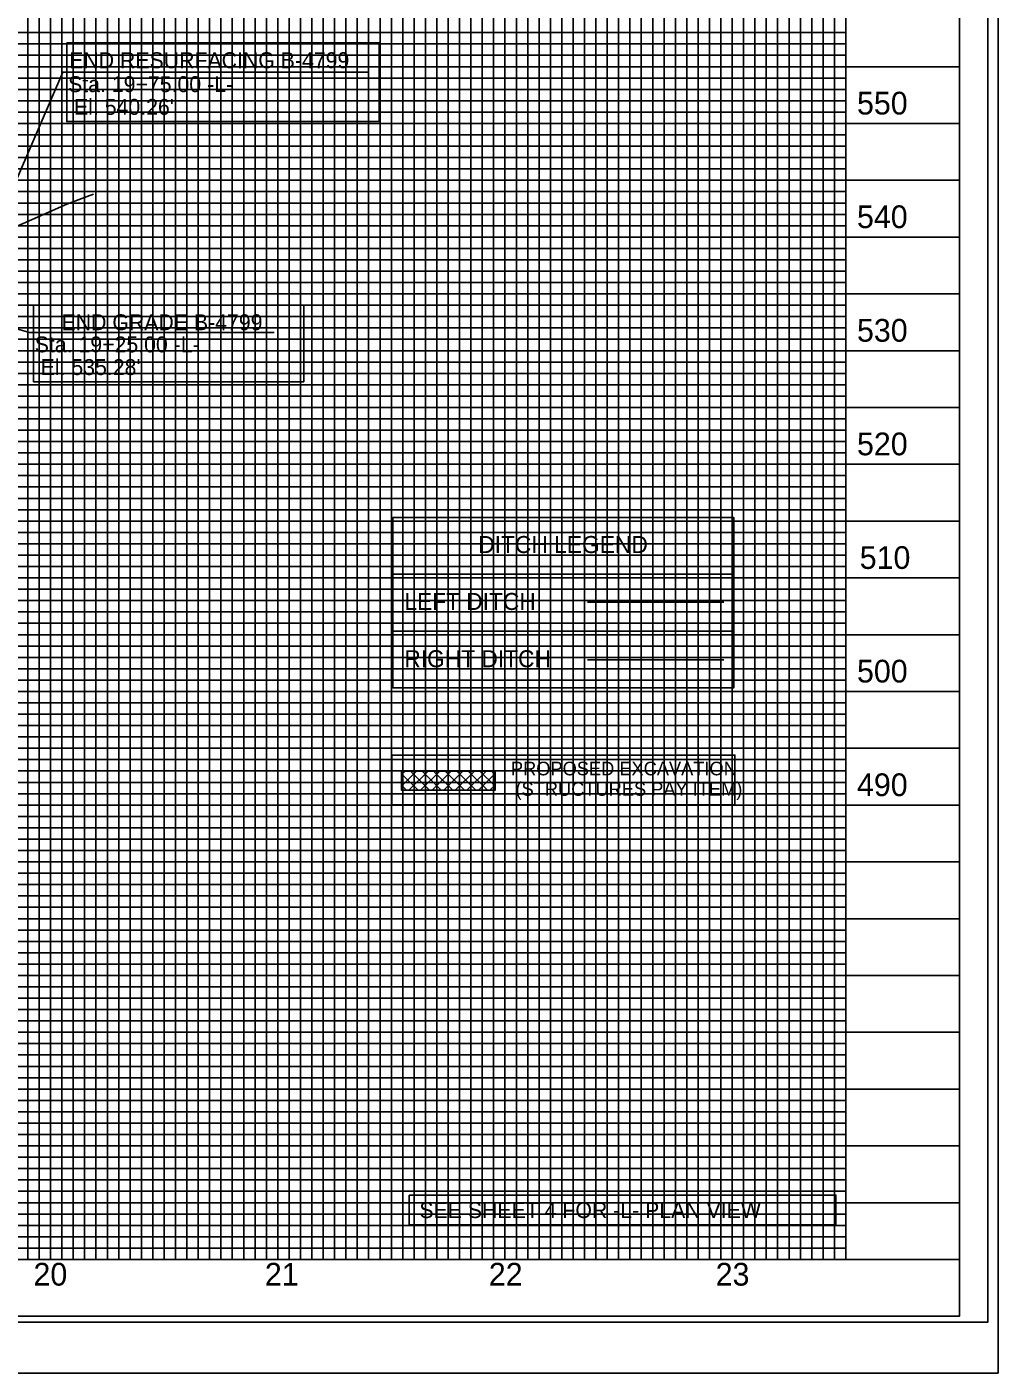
# Model space of a CAD drawing. Extents: x 573715 to 575626, y -55474 to -54374.
# Drawn here: x 574972 to 575399, y -55474 to -54882 of the extents above; entities that cross this region are included whole.
import ezdxf

# ---------------------------------------------------------------- set-up
doc = ezdxf.new("R2010")
doc.units = 0
for name, color, linetype in [('Exist Profile Cell', 7, 'Continuous'), ('Exist Vertical Profile Ground Line', 7, 'Continuous'), ('Exist Vertical Profile Horizontal Axis Label Major', 7, 'Continuous'), ('Exist Vertical Profile Vertical Axis Label', 7, 'Continuous'), ('Prop Grid Mask', 7, 'Continuous'), ('Prop Hatching', 7, 'Continuous'), ('Prop PFL Ditch Label CELL', 7, 'Continuous'), ('Prop Vertical Profile Curve Label', 7, 'Continuous'), ('Prop VPI Label', 7, 'Continuous'), ('Sheet Cutting Line CELL', 7, 'Continuous'), ('Sheet DOT Grid CELL', 7, 'Continuous'), ('Sheet Layout Profile Border', 7, 'Continuous'), ('Sheet Plot Border Inside CELL', 7, 'Continuous'), ('Sheet Plot Border Outside CELL', 7, 'Continuous'), ('Sheet Profile CELL', 7, 'Continuous'), ('Sheet Profile Grid Major CELL', 7, 'Continuous'), ('Sheet Profile Grid Middle CELL', 7, 'Continuous'), ('Sheet Profile Grid Minor CELL', 7, 'Continuous')]:
    doc.layers.add(name, color=color, linetype=linetype)

msp = doc.modelspace()

# ---------------------------------------------------------------- linework, layer by layer
at = {"layer": 'Exist Profile Cell'}
msp.add_line((573982.27, -55224.42), (575001.21, -55224.42), dxfattribs=at)
at = {"layer": 'Exist Vertical Profile Ground Line'}
msp.add_lwpolyline([(574959.85, -54973.04), (574989.51, -54959.89), (574998.39, -54956.62), (575001.21, -54955.58)], dxfattribs=at)
at = {"layer": 'Prop Grid Mask'}
for points in [[(574989.38, -54888.91), (575126.86, -54888.91), (575126.86, -54923.59), (574989.38, -54923.59)], [(574974.7, -55004.37), (575093.67, -55004.37), (575093.67, -55038.13), (574974.7, -55038.13)], [(575132.98, -55097.84), (575282.98, -55097.84), (575282.98, -55122.84), (575132.98, -55122.84)], [(575132.98, -55122.84), (575282.98, -55122.84), (575282.98, -55147.84), (575132.98, -55147.84)], [(575132.98, -55147.84), (575282.98, -55147.84), (575282.98, -55172.84), (575132.98, -55172.84)], [(575132.47, -55224.27), (575283.43, -55224.27), (575283.43, -55202.45), (575132.47, -55202.45)], [(575177.93, -55209.45), (575136.75, -55209.45), (575136.75, -55217.9), (575177.93, -55217.9)], [(575140.11, -55396.07), (575327.9, -55396.07), (575327.9, -55409.2), (575140.11, -55409.2)]]:
    msp.add_lwpolyline(points, close=True, dxfattribs=at)
at = {"layer": 'Prop Hatching'}
for p, q in [((575136.75, -55210.98), (575138.28, -55209.45)), ((575136.75, -55216.07), (575143.37, -55209.45)), ((575136.75, -55210.63), (575144.02, -55217.9)), ((575140.02, -55217.9), (575148.46, -55209.45)), ((575140.67, -55209.45), (575149.12, -55217.9)), ((575145.11, -55217.9), (575153.55, -55209.45)), ((575145.76, -55209.45), (575154.21, -55217.9)), ((575150.2, -55217.9), (575158.65, -55209.45)), ((575150.85, -55209.45), (575159.3, -55217.9)), ((575155.29, -55217.9), (575163.74, -55209.45)), ((575155.94, -55209.45), (575164.39, -55217.9)), ((575160.38, -55217.9), (575168.83, -55209.45)), ((575161.04, -55209.45), (575169.48, -55217.9)), ((575165.48, -55217.9), (575173.92, -55209.45)), ((575166.13, -55209.45), (575174.57, -55217.9)), ((575170.57, -55217.9), (575177.93, -55210.54)), ((575171.22, -55209.45), (575177.93, -55216.16)), ((575176.31, -55209.45), (575177.93, -55211.07)), ((575136.75, -55215.72), (575138.93, -55217.9)), ((575175.66, -55217.9), (575177.93, -55215.63))]:
    msp.add_line(p, q, dxfattribs=at)
at = {"layer": 'Prop PFL Ditch Label CELL'}
for p, q in [((575218.53, -55135.14), (575278.53, -55135.14)), ((575218.53, -55160.49), (575278.53, -55160.49)), ((575132.98, -55162.84), (575132.98, -55162.84))]:
    msp.add_line(p, q, dxfattribs=at)
at = {"layer": 'Prop Vertical Profile Curve Label'}
for p, q in [((574987.75, -54901.88), (574957.02, -54972.88)), ((574987.75, -54901.88), (575121.7, -54901.88)), ((574907.27, -54998.02), (574973.06, -55016.41)), ((574973.06, -55016.41), (575080.66, -55016.41))]:
    msp.add_line(p, q, dxfattribs=at)
at = {"layer": 'Sheet Cutting Line CELL'}
msp.add_line((573715.27, -55474.42), (575399.27, -55474.42), dxfattribs=at)
at = {"layer": 'Sheet DOT Grid CELL'}
for p, q in [((574982.27, -54399.42), (574982.27, -55424.42)), ((575032.27, -54399.42), (575032.27, -55424.42)), ((575082.27, -54399.42), (575082.27, -55424.42)), ((575132.27, -54399.42), (575132.27, -55424.42)), ((575182.27, -55424.42), (575182.27, -54536.97)), ((575232.27, -55424.42), (575232.27, -54536.97)), ((575282.27, -55424.42), (575282.27, -54536.97)), ((575332.27, -55424.42), (575332.27, -54536.97)), ((573882.27, -54924.42), (575382.27, -54924.42)), ((573882.27, -54974.42), (575382.27, -54974.42)), ((573882.27, -55024.42), (575382.27, -55024.42)), ((573882.27, -55074.42), (575382.27, -55074.42)), ((573882.27, -55124.42), (575382.27, -55124.42)), ((573882.27, -55174.42), (575382.27, -55174.42)), ((573882.27, -55224.42), (575382.27, -55224.42)), ((573882.27, -55274.42), (575382.27, -55274.42)), ((573882.27, -55324.42), (575382.27, -55324.42)), ((573882.27, -55374.42), (575382.27, -55374.42))]:
    msp.add_line(p, q, dxfattribs=at)
at = {"layer": 'Sheet Layout Profile Border'}
msp.add_lwpolyline([(573932.27, -54399.42), (573932.27, -55424.42), (575332.27, -55424.42), (575332.27, -54536.97), (575182.22, -54536.97), (575182.22, -54399.42)], close=True, dxfattribs=at)
at = {"layer": 'Sheet Plot Border Inside CELL'}
msp.add_lwpolyline([(575394.77, -54396.87), (573728.27, -54396.87), (573728.27, -55451.97), (575394.77, -55451.97)], close=True, dxfattribs=at)
msp.add_lwpolyline([(575394.77, -54396.87), (573728.27, -54396.87), (573728.27, -55451.97), (575394.77, -55451.97)], close=True, dxfattribs=at)
at = {"layer": 'Sheet Plot Border Outside CELL'}
msp.add_lwpolyline([(575399.27, -54374.42), (573715.27, -54374.42), (573715.27, -55474.42), (575399.27, -55474.42)], close=True, dxfattribs=at)
at = {"layer": 'Sheet Profile CELL'}
msp.add_line((575382.27, -55424.42), (573882.27, -55424.42), dxfattribs=at)
msp.add_lwpolyline([(575382.27, -54399.42), (573882.27, -54399.42), (573882.27, -55449.42), (575382.27, -55449.42)], close=True, dxfattribs=at)
at = {"layer": 'Sheet Profile Grid Major CELL'}
for points in [[(574932.27, -55424.42), (574982.27, -55424.42), (574982.27, -54399.42), (575032.27, -54399.42), (575032.27, -55424.42), (575082.27, -55424.42), (575082.27, -54399.42), (575132.27, -54399.42), (575132.27, -55424.42), (575182.27, -55424.42), (575182.27, -54399.42), (575208.57, -54399.42)], [(575232.27, -54536.97), (575232.27, -55424.42), (575282.27, -55424.42), (575282.27, -54536.97)], [(575332.27, -54536.97), (575332.27, -55424.42), (575382.27, -55424.42)], [(575382.27, -54974.42), (573882.27, -54974.42), (573882.27, -54924.42), (575382.27, -54924.42)], [(575382.27, -55074.42), (573882.27, -55074.42), (573882.27, -55024.42), (575382.27, -55024.42)], [(575382.27, -55174.42), (573882.27, -55174.42), (573882.27, -55124.42), (575382.27, -55124.42)], [(575382.27, -55274.42), (573882.27, -55274.42), (573882.27, -55224.42), (575382.27, -55224.42)], [(575382.27, -55374.42), (573882.27, -55374.42), (573882.27, -55324.42), (575382.27, -55324.42)]]:
    msp.add_lwpolyline(points, dxfattribs=at)
at = {"layer": 'Sheet Profile Grid Middle CELL'}
for points in [[(574957.27, -54399.42), (575007.27, -54399.42), (575007.27, -55424.42), (575057.27, -55424.42), (575057.27, -54399.42), (575107.27, -54399.42), (575107.27, -55424.42), (575157.27, -55424.42), (575157.27, -54399.42)], [(575207.27, -54536.97), (575207.27, -55424.42), (575257.27, -55424.42), (575257.27, -54536.97)], [(575307.27, -54536.97), (575307.27, -55424.42)], [(575382.27, -54899.42), (573882.27, -54899.42), (573882.27, -54949.42), (575382.27, -54949.42)], [(575382.27, -54999.42), (573882.27, -54999.42), (573882.27, -55049.42), (575382.27, -55049.42)], [(575382.27, -55099.42), (573882.27, -55099.42), (573882.27, -55149.42), (575382.27, -55149.42)], [(575382.27, -55199.42), (573882.27, -55199.42), (573882.27, -55249.42), (575382.27, -55249.42)], [(575382.27, -55299.42), (573882.27, -55299.42), (573882.27, -55349.42), (575382.27, -55349.42)], [(575382.27, -55399.42), (573882.27, -55399.42)]]:
    msp.add_lwpolyline(points, dxfattribs=at)
at = {"layer": 'Sheet Profile Grid Minor CELL'}
for points in [[(574967.27, -55424.42), (574972.27, -55424.42), (574972.27, -54399.42)], [(574977.27, -54399.42), (574977.27, -55424.42), (574987.27, -55424.42), (574987.27, -54399.42)], [(574992.27, -54399.42), (574992.27, -55424.42), (574997.27, -55424.42), (574997.27, -54399.42)], [(575002.27, -54399.42), (575002.27, -55424.42), (575012.27, -55424.42), (575012.27, -54399.42)], [(575017.27, -54399.42), (575017.27, -55424.42), (575022.27, -55424.42), (575022.27, -54399.42)], [(575027.27, -54399.42), (575027.27, -55424.42), (575037.27, -55424.42), (575037.27, -54399.42)], [(575042.27, -54399.42), (575042.27, -55424.42), (575047.27, -55424.42), (575047.27, -54399.42)], [(575052.27, -54399.42), (575052.27, -55424.42), (575062.27, -55424.42), (575062.27, -54399.42)], [(575067.27, -54399.42), (575067.27, -55424.42), (575072.27, -55424.42), (575072.27, -54399.42)], [(575077.27, -54399.42), (575077.27, -55424.42), (575087.27, -55424.42), (575087.27, -54399.42)], [(575092.27, -54399.42), (575092.27, -55424.42), (575097.27, -55424.42), (575097.27, -54399.42)], [(575102.27, -54399.42), (575102.27, -55424.42), (575112.27, -55424.42), (575112.27, -54399.42)], [(575117.27, -54399.42), (575117.27, -55424.42), (575122.27, -55424.42), (575122.27, -54399.42)], [(575127.27, -54399.42), (575127.27, -55424.42), (575137.27, -55424.42), (575137.27, -54399.42)], [(575142.27, -54399.42), (575142.27, -55424.42), (575147.27, -55424.42), (575147.27, -54399.42)], [(575152.27, -54399.42), (575152.27, -55424.42), (575162.27, -55424.42), (575162.27, -54399.42)], [(575167.27, -54399.42), (575167.27, -55424.42), (575172.27, -55424.42), (575172.27, -54399.42)], [(575177.27, -54399.42), (575177.27, -55424.42), (575187.27, -55424.42), (575187.27, -54536.97)], [(575192.27, -54536.97), (575192.27, -55424.42), (575197.27, -55424.42), (575197.27, -54536.97)], [(575202.27, -54536.97), (575202.27, -55424.42), (575212.27, -55424.42), (575212.27, -54536.97)], [(575217.27, -54536.97), (575217.27, -55424.42), (575222.27, -55424.42), (575222.27, -54536.97)], [(575227.27, -54536.97), (575227.27, -55424.42), (575237.27, -55424.42), (575237.27, -54536.97)], [(575242.27, -54536.97), (575242.27, -55424.42), (575247.27, -55424.42), (575247.27, -54536.97)], [(575252.27, -54536.97), (575252.27, -55424.42), (575262.27, -55424.42), (575262.27, -54536.97)], [(575267.27, -54536.97), (575267.27, -55424.42)], [(575267.27, -55424.42), (575272.27, -55424.42), (575272.27, -54536.97)], [(575277.27, -54536.97), (575277.27, -55424.42), (575287.27, -55424.42), (575287.27, -54536.97)], [(575292.27, -54536.97), (575292.27, -55424.42), (575297.27, -55424.42), (575297.27, -54536.97)], [(575302.27, -54536.97), (575302.27, -55424.42), (575312.27, -55424.42), (575312.27, -54536.97)], [(575317.27, -54536.97), (575317.27, -55424.42), (575322.27, -55424.42), (575322.27, -54536.97)], [(575327.27, -54536.97), (575327.27, -55424.42), (575337.27, -55424.42)], [(575332.27, -54884.42), (573932.27, -54884.42), (573932.27, -54889.42), (575332.27, -54889.42)], [(575332.27, -54894.42), (573932.27, -54894.42), (573932.27, -54904.42), (575332.27, -54904.42)], [(575332.27, -54909.42), (573932.27, -54909.42), (573932.27, -54914.42), (575332.27, -54914.42)], [(575332.27, -54919.42), (573932.27, -54919.42)], [(573932.27, -54929.42), (575332.27, -54929.42)], [(575332.27, -54934.42), (573932.27, -54934.42), (573932.27, -54939.42), (575332.27, -54939.42)], [(575332.27, -54944.42), (573932.27, -54944.42), (573932.27, -54954.42), (575332.27, -54954.42)], [(575332.27, -54959.42), (573932.27, -54959.42), (573932.27, -54964.42), (575332.27, -54964.42)], [(575332.27, -54969.42), (573932.27, -54969.42), (573932.27, -54979.42), (575332.27, -54979.42)], [(575332.27, -54984.42), (573932.27, -54984.42), (573932.27, -54989.42), (575332.27, -54989.42)], [(575332.27, -54994.42), (573932.27, -54994.42), (573932.27, -55004.42), (575332.27, -55004.42)], [(575332.27, -55009.42), (573932.27, -55009.42), (573932.27, -55014.42), (575332.27, -55014.42)], [(575332.27, -55019.42), (573932.27, -55019.42), (573932.27, -55029.42), (575332.27, -55029.42)], [(575332.27, -55034.42), (573932.27, -55034.42), (573932.27, -55039.42), (575332.27, -55039.42)], [(575332.27, -55044.42), (573932.27, -55044.42), (573932.27, -55054.42), (575332.27, -55054.42)], [(575332.27, -55059.42), (573932.27, -55059.42), (573932.27, -55064.42), (575332.27, -55064.42)], [(575332.27, -55069.42), (573932.27, -55069.42), (573932.27, -55079.42), (575332.27, -55079.42)], [(575332.27, -55084.42), (573932.27, -55084.42), (573932.27, -55089.42), (575332.27, -55089.42)], [(575332.27, -55094.42), (573932.27, -55094.42), (573932.27, -55104.42), (575332.27, -55104.42)], [(575332.27, -55109.42), (573932.27, -55109.42), (573932.27, -55114.42), (575332.27, -55114.42)], [(575332.27, -55119.42), (573932.27, -55119.42), (573932.27, -55129.42), (575332.27, -55129.42)], [(575332.27, -55134.42), (573932.27, -55134.42), (573932.27, -55139.42), (575332.27, -55139.42)], [(575332.27, -55144.42), (573932.27, -55144.42), (573932.27, -55154.42), (575332.27, -55154.42)], [(575332.27, -55159.42), (573932.27, -55159.42), (573932.27, -55164.42), (575332.27, -55164.42)], [(575332.27, -55169.42), (573932.27, -55169.42), (573932.27, -55179.42), (575332.27, -55179.42)], [(575332.27, -55184.42), (573932.27, -55184.42), (573932.27, -55189.42), (575332.27, -55189.42)], [(575332.27, -55194.42), (573932.27, -55194.42), (573932.27, -55204.42), (575332.27, -55204.42)], [(575332.27, -55209.42), (573932.27, -55209.42), (573932.27, -55214.42), (575332.27, -55214.42)], [(575332.27, -55219.42), (573932.27, -55219.42)], [(573932.27, -55229.42), (575332.27, -55229.42)], [(575332.27, -55234.42), (573932.27, -55234.42), (573932.27, -55239.42), (575332.27, -55239.42)], [(575332.27, -55244.42), (573932.27, -55244.42)], [(573932.27, -55254.42), (575332.27, -55254.42)], [(575332.27, -55259.42), (573932.27, -55259.42), (573932.27, -55264.42), (575332.27, -55264.42)], [(575332.27, -55269.42), (573932.27, -55269.42), (573932.27, -55279.42), (575332.27, -55279.42)], [(575332.27, -55284.42), (573932.27, -55284.42), (573932.27, -55289.42), (575332.27, -55289.42)], [(575332.27, -55294.42), (573932.27, -55294.42), (573932.27, -55304.42), (575332.27, -55304.42)], [(575332.27, -55309.42), (573932.27, -55309.42), (573932.27, -55314.42), (575332.27, -55314.42)], [(575332.27, -55319.42), (573932.27, -55319.42), (573932.27, -55329.42), (575332.27, -55329.42)], [(575332.27, -55334.42), (573932.27, -55334.42), (573932.27, -55339.42), (575332.27, -55339.42)], [(575332.27, -55344.42), (573932.27, -55344.42), (573932.27, -55354.42), (575332.27, -55354.42)], [(575332.27, -55359.42), (573932.27, -55359.42), (573932.27, -55364.42), (575332.27, -55364.42)], [(575332.27, -55369.42), (573932.27, -55369.42), (573932.27, -55379.42), (575332.27, -55379.42)], [(575332.27, -55384.42), (573932.27, -55384.42), (573932.27, -55389.42), (575332.27, -55389.42)], [(575332.27, -55394.42), (573932.27, -55394.42), (573932.27, -55404.42), (575332.27, -55404.42)], [(575332.27, -55409.42), (573932.27, -55409.42), (573932.27, -55414.42), (575332.27, -55414.42)], [(575332.27, -55419.42), (573932.27, -55419.42)]]:
    msp.add_lwpolyline(points, dxfattribs=at)

# ---------------------------------------------------------------- texts
at = {"layer": 'Exist Vertical Profile Horizontal Axis Label Major'}
for s, p in [('20', (574974.76, -55435.92)), ('21', (575076.6, -55435.92)), ('22', (575175.15, -55435.92)), ('23', (575274.99, -55435.92))]:
    msp.add_text(s, height=10, dxfattribs=at).set_placement(p)
at = {"layer": 'Exist Vertical Profile Vertical Axis Label'}
for s, p in [('550', (575337.18, -54920.47)), ('540', (575337.18, -54970.47)), ('530', (575337.18, -55020.47)), ('520', (575337.18, -55070.47)), ('510', (575338.38, -55120.47)), ('500', (575337.18, -55170.47)), ('490', (575337.18, -55220.47))]:
    msp.add_text(s, height=10, dxfattribs=at).set_placement(p)
at = {"layer": 'Prop PFL Ditch Label CELL'}
for s, height, p in [('DITCH LEGEND', 7.5, (575170.48, -55113.49)), ('LEFT DITCH', 7.485, (575137.98, -55138.54)), ('RIGHT DITCH', 7.485, (575137.98, -55163.74))]:
    msp.add_text(s, height=height, dxfattribs=at).set_placement(p)
at = {"layer": 'Prop Vertical Profile Curve Label'}
for s, p in [('END RESURFACING B-4799', (574990.48, -54900.08)), ('Sta. 19+75.00 -L-', (574989.99, -54910.61)), (" El. 540.26'", (574989.99, -54920.61)), ('END GRADE B-4799', (574987.11, -55015.41)), ('Sta. 19+25.00 -L-', (574975.31, -55025.15)), (" El. 535.28'", (574975.31, -55035.15))]:
    msp.add_text(s, height=7, dxfattribs=at).set_placement(p)
for s, p in [('PROPOSED EXCAVATION', (575184.89, -55211.33)), ('(STRUCTURES PAY ITEM)', (575186.89, -55220.33))]:
    msp.add_text(s, height=6, rotation=0.00001, dxfattribs=at).set_placement(p)
at = {"layer": 'Prop VPI Label'}
msp.add_text('SEE SHEET 4 FOR -L- PLAN VIEW', height=7, dxfattribs=at).set_placement((575144.59, -55406.19))

doc.saveas('drawing.dxf')
